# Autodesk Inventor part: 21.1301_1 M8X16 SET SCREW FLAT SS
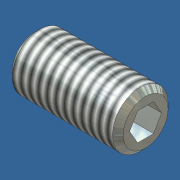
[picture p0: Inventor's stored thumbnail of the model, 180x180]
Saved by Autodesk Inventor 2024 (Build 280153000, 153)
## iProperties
Created: 2006-02
Material: Stainless Steel
Description: M8X16 SET SCREW FLAT DIN 913
Document SubType Name: Modeling
Standard: DIN 913
Designer: Andy Moles
Standards Organization: DIN
Language: en-US
Size Designation: M8 x 16
Categories: <MemberInstance><Categories><Category DisplayName="Fasteners" InternalName="e4da775c-781d-43d5-af7c-5136215cf5a6" Mnemonic="FSTN"><Category DisplayName="Bolts"
Density: 7.75 g/cm^3
Mass: 5.53264 g
Surface Area: 5.51599 cm^2
Volume: 0.713889 cm^3
Part Number: 21.1301_1 M8X16 SET SCREW FLAT SS
Appearance: Steel
Author: Andy Moles
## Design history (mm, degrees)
revolve "Body" stored, may be unused: angle "d6" = 90 deg
sketch "Sketch2"
  geometry: L1 (-1.155, 2)-(1.155, 2); L2 (1.155, 2)-(2.309, 0); L3 (2.309, 0)-(1.155, -2); L4 (1.155, -2)-(-1.155, -2); L5 (-1.155, -2)-(-2.309, 0); L6 (-2.309, 0)-(-1.155, 2); 3 further points
  constraints: 12 end point, 1 coincident, 1 horizontal, 13 other
extrude "Slot" join sketch "Sketch2" taper "d7" = 0 deg; stored distance "d21" = 10
workaxis "Work Axis1"
workplane "Work Plane1"
body "Solid1"
feature "Thread" dims "d8" = 16 (= NLG), "d9" = 0
chamfer "Chamfer1" distance "d10" = 0.76681 (= -0.5 x GD1 + 0.5 x NND); stored, may be unused: angle "d11" = 45 deg (= FAWI), second distance "d34" = 0.76681 (= -0.5 x GD1 + 0.5 x NND)
chamfer "Chamfer2" distance "d12" = 0.76681 (= -0.5 x GD1 + 0.5 x NND); stored, may be unused: angle "d13" = 45 deg (= FAWI), second distance "d35" = 0.76681 (= -0.5 x GD1 + 0.5 x NND); dims "INTI" = 5 [user parameter; used in 1 equation term]
sketch "Sketch1"
  geometry: L1 (0, 0)-(9.667, 0); L2 (16, 2.309)-(16, 4); L3 (16, 4)-(0, 4); L4 (16, 2.309)-(11, 2.309); L5 (11, 2.309)-(9.667, 0); L6 (0, -0.4)-(0, 5.2) reference; L7 (0, 4)-(0, 0)
  constraints: 13 end point, 3 parallel, 1 collinear, 1 perpendicular, 1 point on line
  dimensions: "d0" = 5 distance of L2.start L4.end (= INTI); "d1" = 60 deg angle of L5 L1; "d2" = 8 diameter of L3 L1 (= NND); "d3" = 4.6188 diameter of L4 L1 (= 1.1547 x SW); "d5" = 16 distance from line of L2 L3.end (= NLG)
other parameters: "NND" = 8 [user parameter; used in 5 equation terms], "NLG" = 16 [user parameter; used in 2 equation terms], "FAWI" = 45 deg [user parameter; used in 2 equation terms], "SW" = 4 [user parameter; used in 2 equation terms], "GD1" = 6.46637 (= THREADDIA - 1.2269 x PTC) [user parameter; used in 4 equation terms], "d4" = 0, "SPD" = 5.5 [user parameter], "d33" = 0, "d36" = 0, "GUL" = 0.76681 (= 0.61345 x PTC) [user parameter], "TPU" = 8 (computed from PTC) [user parameter], "TOA" = 30 deg [user parameter], "THREADDIA" = 8 [user parameter; used in 1 equation term], "PTC" = 1.25 [user parameter; used in 4 equation terms], "FAWI1" = 45 deg [user parameter], "GAL" = 0.76681 (= 0.61345 x PTC) [user parameter], "E0" = 4.62 (= 1.155 x SW) [user parameter]
